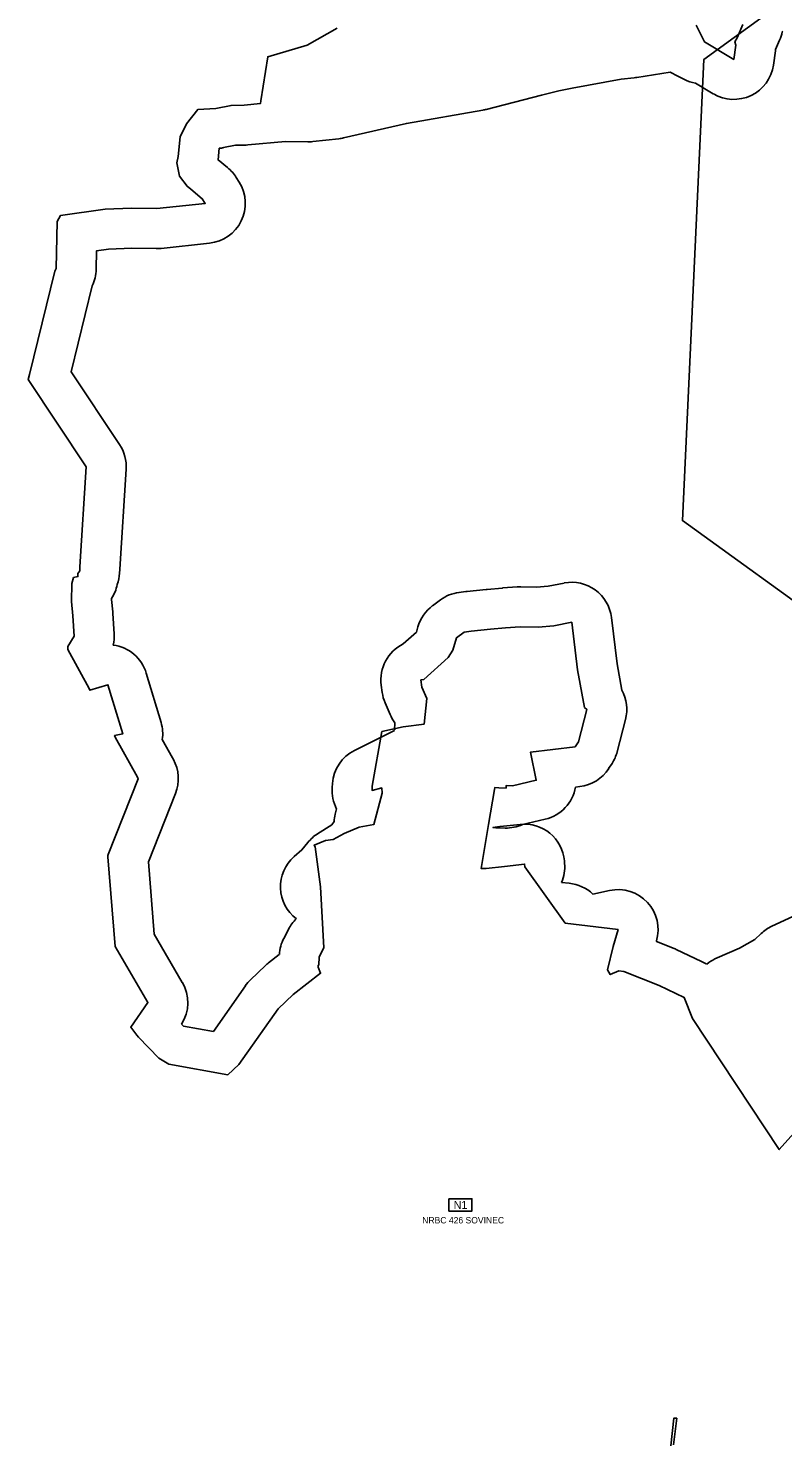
# Model space of a CAD drawing. Extents: x -547623 to -532764, y -1096714 to -1086523.
# Drawn here: x -545672 to -544729, y -1094393 to -1092629 of the extents above; entities that cross this region are included whole.
import ezdxf

# ---------------------------------------------------------------- set-up
doc = ezdxf.new("R2010")
doc.units = 0
for name, color, linetype in [('Vrstva 22', 7, 'Continuous'), ('Vrstva 23', 7, 'Continuous'), ('Vrstva 25', 7, 'Continuous'), ('Vrstva 27', 7, 'Continuous'), ('Vrstva 36', 7, 'Continuous')]:
    doc.layers.add(name, color=color, linetype=linetype)

msp = doc.modelspace()

# ---------------------------------------------------------------- linework, layer by layer
at = {"layer": 'Vrstva 22'}
msp.add_lwpolyline([(-544570.5, -1092481.5), (-544170.3, -1093428.5), (-544273.3, -1093653.1), (-544324, -1093623.3), (-544281.5, -1093528.2), (-544330.2, -1093474.1), (-544403.4, -1093457), (-544439.5, -1093470.8), (-544456.8, -1093510.2), (-544479, -1093516.1), (-544854.9, -1093244.4), (-544828, -1092667.9), (-544697.7, -1092572.9), (-544693.4, -1092540.6), (-544716.6, -1092493.7), (-544691.5, -1092459.6), (-544570.5, -1092481.5)], dxfattribs=at)
at = {"layer": 'Vrstva 23'}
for p, q in [((-544738.3, -1092655.5), (-544733.3, -1092644)), ((-544730.1, -1092633.5), (-544729.4, -1092632.5)), ((-544741.1, -1092675.1), (-544738.5, -1092657)), ((-544838.5, -1092697.6), (-544816.2, -1092710.9)), ((-545316.7, -1092770.6), (-545284.1, -1092767)), ((-545408.7, -1092821.5), (-545412.4, -1092815.6)), ((-545506.5, -1092904.1), (-545445.9, -1092897.6)), ((-545558, -1093305.2), (-545550, -1093180.2)), ((-545558.3, -1093310.2), (-545558, -1093305.3)), ((-545125.5, -1093333), (-545134.1, -1093334.1)), ((-545100, -1093330.4), (-545124.1, -1093332.8)), ((-545080, -1093328.7), (-545099, -1093330.3)), ((-545061.2, -1093327.3), (-545079.4, -1093328.6)), ((-545157.3, -1093343.5), (-545167.1, -1093350.8)), ((-545565.1, -1093386), (-545566.6, -1093360.6)), ((-545506.5, -1093496.8), (-545524.9, -1093435.2)), ((-545231.3, -1093450.2), (-545230.1, -1093459.1)), ((-545226.5, -1093472.2), (-545220.2, -1093486.7)), ((-545214.5, -1093506.6), (-545264.8, -1093531.7)), ((-545214.4, -1093499.7), (-545214.5, -1093503.7)), ((-544936.4, -1093533.3), (-544925.9, -1093493)), ((-545492.1, -1093541.1), (-545504.9, -1093518)), ((-545491.1, -1093543), (-545492.1, -1093541.1)), ((-544947, -1093554.4), (-544942.8, -1093547.9)), ((-545292.3, -1093572.9), (-545292.6, -1093578.1)), ((-544988.4, -1093577.5), (-544982.9, -1093576.8)), ((-545287, -1093604.8), (-545288.7, -1093611.5)), ((-545085.3, -1093628.5), (-545076.5, -1093628.7)), ((-545057.7, -1093624.1), (-545082.8, -1093626.9)), ((-545054.8, -1093624.3), (-545026.2, -1093617.6)), ((-545002.1, -1093672.9), (-545002.3, -1093669.7)), ((-544996.5, -1093697.7), (-545006, -1093696.8)), ((-544945.9, -1093706.8), (-544966.6, -1093711.4)), ((-545347.3, -1093755.4), (-545353.2, -1093766.7)), ((-545358.7, -1093786.9), (-545372.1, -1093797.3)), ((-544831.1, -1093795.3), (-544862.5, -1093780.4)), ((-545375.9, -1093800.5), (-545394.6, -1093818.3))]:
    msp.add_line(p, q, dxfattribs=at)
for points in [[(-545100.2, -1092730.4), (-545030.9, -1092712.5), (-545009.3, -1092707.2), (-544992.5, -1092704), (-544931.3, -1092692.4), (-544915.2, -1092690.9)], [(-544911.8, -1092690.5), (-544870.2, -1092683.8), (-544860.4, -1092688.8)], [(-544860.4, -1092688.9), (-544855.4, -1092691.4), (-544852.3, -1092693)], [(-545278.3, -1092766), (-545199.9, -1092747.9), (-545104.1, -1092731.2)], [(-545423.3, -1092803.2), (-545435.3, -1092793.5), (-545433.8, -1092779)], [(-545428.4, -1092778.2), (-545413.5, -1092775.3), (-545401.9, -1092775.1)], [(-545398.2, -1092774.8), (-545350.8, -1092770.4), (-545322.9, -1092770.8)], [(-545587.6, -1092930.3), (-545587.1, -1092907.1), (-545572, -1092905), (-545542.9, -1092903.9), (-545512.7, -1092904.4)], [(-545558.3, -1093149.3), (-545618.7, -1093058.5), (-545592.4, -1092950.9)], [(-545002.5, -1093322.4), (-545022.8, -1093326.2), (-545037, -1093327.6), (-545056.6, -1093327.2)], [(-545566.8, -1093358.4), (-545568.4, -1093343.2), (-545568.4, -1093341.6)], [(-544930.5, -1093456.2), (-544936.5, -1093423.4), (-544943.6, -1093365.4)], [(-545185.4, -1093377.2), (-545187.3, -1093383.8), (-545203.8, -1093398.6)], [(-545479.9, -1093821.6), (-545515.1, -1093761.4), (-545522.2, -1093670.8), (-545488.4, -1093585.6)], [(-545290.2, -1093620.6), (-545293.2, -1093624.6), (-545310.8, -1093635.8)], [(-545082.9, -1093626.9), (-545091.6, -1093627.9), (-545091, -1093628)], [(-545322.9, -1093646.7), (-545330.5, -1093656.1), (-545340, -1093664.4)], [(-544704.7, -1093726.5), (-544717, -1093739.2), (-544743, -1093751.4)], [(-544865.1, -1093779.3), (-544887.4, -1093770.3), (-544887.2, -1093769.8)], [(-544756.3, -1093760.6), (-544764.1, -1093768.1), (-544783.3, -1093778.9), (-544811.5, -1093791)], [(-544821.7, -1093796.8), (-544824.5, -1093799)], [(-545401.1, -1093825.9), (-545441.1, -1093882.9), (-545478.5, -1093876.2), (-545480.8, -1093873.8)]]:
    msp.add_lwpolyline(points, dxfattribs=at)
for centre, start, end in [((-544779.2, -1092624.1), 336.494, 349.1271), ((-544788, -1092649.9), 351.7946, 353.5151), ((-544790.6, -1092667.9), 239.2389, 351.7946), ((-544919.8, -1092641.1), 275.2056, 279.1028), ((-544837.7, -1092644.3), 243.0155, 243.028), ((-544829.5, -1092648.5), 242.9247, 259.6614), ((-545112.6, -1092681.9), 279.8671, 284.4331), ((-545289.6, -1092717.3), 276.2148, 283.0392), ((-545438.1, -1092729.2), 274.8718, 281.2179), ((-545402.8, -1092725.1), 271.1408, 275.3264), ((-545322.2, -1092720.9), 269.1388, 276.2148), ((-545454.9, -1092842), 31.8565, 50.8882), ((-545451.2, -1092847.9), 276.1075, 31.8565), ((-545511.8, -1092854.4), 268.9847, 276.1075), ((-545637.6, -1092929.4), 334.5, 358.9069), ((-545599.9, -1093177), 356.3255, 33.6791), ((-545608.2, -1093307), 339.7155, 356.316), ((-545607.9, -1093302), 356.316, 356.3255), ((-545610.3, -1093314.4), 326.9849, 348.5168), ((-545118.9, -1093382.6), 95.8916, 97.4941), ((-545094.8, -1093380.1), 94.7636, 95.8916), ((-545075.9, -1093378.5), 94.099, 94.7636), ((-545057.6, -1093377.2), 88.8267, 94.099), ((-544993.2, -1093371.5), 7.0039, 100.6751), ((-545137.3, -1093390.9), 126.512, 164.0497), ((-545127.5, -1093383.7), 97.4941, 126.512), ((-545616.6, -1093363.6), 3.4206, 5.9663), ((-545615, -1093389), 347.4093, 3.4206), ((-545572.8, -1093449.5), 16.6318, 82.4869), ((-545181.7, -1093443.5), 116.1197, 187.662), ((-544974.3, -1093480.4), 345.4375, 28.9048), ((-545180.5, -1093452.4), 187.662, 203.3321), ((-545174.3, -1093466.9), 203.3321, 216.9676), ((-545554.4, -1093511.1), 352.0228, 16.6318), ((-545164.5, -1093504.9), 178.5498, 181.8409), ((-545164.4, -1093501), 175.3978, 178.5498), ((-545535.9, -1093565.2), 28.8461, 28.9276), ((-545534.9, -1093567.1), 338.331, 28.8461), ((-545242.4, -1093576.4), 116.5735, 175.9858), ((-544984.8, -1093520.8), 327.0763, 345.4375), ((-544988.9, -1093527.2), 276.9131, 327.0763), ((-545242.8, -1093581.6), 175.9858, 207.7449), ((-545037.6, -1093568.9), 283.2155, 350.1418), ((-545240.4, -1093624.1), 165.3672, 175.9708), ((-545084.1, -1093578.5), 262.0716, 268.5695), ((-545077.2, -1093676.6), 96.3502, 96.4504), ((-545075.2, -1093578.7), 268.5695, 294.1821), ((-545052.2, -1093673.8), 4.7931, 96.3502), ((-545283.9, -1093678), 122.5187, 141.3025), ((-545307.3, -1093702.2), 130.9043, 233.0071), ((-545051.9, -1093677.1), 336.7432, 4.7931), ((-545001.2, -1093747.5), 46.2482, 84.5691), ((-544935.2, -1093755.6), 343.5003, 102.3722), ((-545302.9, -1093778.3), 133.6234, 152.6901), ((-544721.7, -1093796.6), 115.2407, 133.9137), ((-545308.7, -1093789.6), 152.6901, 176.8401), ((-544883.8, -1093825.6), 64.7136, 68.0222), ((-544791.9, -1093837), 113.1828, 126.5915), ((-545341.5, -1093836.8), 127.8058, 133.4586), ((-544852.5, -1093840.5), 56.0571, 64.7136), ((-545523, -1093846.9), 327.4678, 30.3468), ((-545360.2, -1093854.6), 133.4586, 145.003)]:
    msp.add_arc(centre, 50, start, end, dxfattribs=at)
at = {"layer": 'Vrstva 25'}
for points in [[(-544837.6, -1092625), (-544827.3, -1092646.1), (-544790.6, -1092667.9), (-544788, -1092649.9), (-544789.4, -1092646), (-544786.5, -1092640.9), (-544779.2, -1092624.1)], [(-544685.6, -1093976.9), (-544733.7, -1094030.6), (-544842.2, -1093866.8), (-544852.5, -1093840.5), (-544883.8, -1093825.6), (-544928, -1093807.8), (-544934.4, -1093807.3), (-544945, -1093811.9), (-544948.6, -1093806), (-544941.4, -1093776.7), (-544935.2, -1093755.6), (-545001.2, -1093747.5), (-545051.9, -1093677.1), (-545052.2, -1093673.8), (-545077.2, -1093676.6), (-545100.1, -1093679.2), (-545106.4, -1093679.1), (-545097.2, -1093624.2), (-545089.7, -1093580.7), (-545089.1, -1093577.8), (-545084.1, -1093578.5), (-545075.2, -1093578.7), (-545075.1, -1093575.4), (-545067, -1093575.8), (-545037.6, -1093568.9), (-545044.8, -1093534), (-544988.9, -1093527.2), (-544984.8, -1093520.8), (-544974.3, -1093480.4), (-544977.3, -1093477.9), (-544985.9, -1093431), (-544993.2, -1093371.5), (-545015.7, -1093375.8), (-545035.1, -1093377.7), (-545057.6, -1093377.2), (-545075.9, -1093378.5), (-545094.8, -1093380.1), (-545118.9, -1093382.6), (-545127.5, -1093383.7), (-545137.3, -1093390.9), (-545141.7, -1093406.4), (-545147.8, -1093415.5), (-545178.1, -1093442.8), (-545181.7, -1093443.5), (-545180.5, -1093452.4), (-545174.3, -1093466.9), (-545177.8, -1093498.7), (-545203.9, -1093502.2), (-545230.5, -1093508.2), (-545242.4, -1093576.4), (-545242.8, -1093581.6), (-545230.7, -1093578.5), (-545230.2, -1093585.1), (-545240.4, -1093624.1), (-545258.7, -1093627.4), (-545277.8, -1093635.4), (-545291.5, -1093643.1), (-545300.9, -1093644.3), (-545315.3, -1093650.2), (-545313.8, -1093652.2), (-545307.3, -1093702.2), (-545302.9, -1093778.3), (-545308.7, -1093789.6), (-545309.2, -1093799.9), (-545310, -1093799.9), (-545310, -1093802.7), (-545307, -1093810.1), (-545341.5, -1093836.8), (-545360.2, -1093854.6), (-545409.1, -1093924.4), (-545423, -1093937), (-545496.6, -1093923.8), (-545509.3, -1093916.2), (-545534.7, -1093890.2), (-545536.7, -1093887.6), (-545544.4, -1093877.5), (-545523, -1093846.9), (-545564, -1093776.8), (-545572.9, -1093664.6), (-545573, -1093663.1), (-545572.5, -1093661.9), (-545534.9, -1093567.1), (-545535.9, -1093565.2), (-545563.7, -1093515), (-545564.6, -1093513.2), (-545554.4, -1093511.1), (-545572.8, -1093449.5), (-545595.4, -1093456.4), (-545596.5, -1093454.3), (-545623, -1093405.3), (-545622.8, -1093401.6), (-545615, -1093389), (-545616.6, -1093363.6), (-545618.5, -1093345.4), (-545618.1, -1093322.8), (-545615.9, -1093315.6), (-545610.3, -1093314.4), (-545610.7, -1093310.6), (-545608.2, -1093307), (-545607.9, -1093302), (-545599.9, -1093177), (-545672.5, -1093068), (-545670.9, -1093061.7), (-545639.4, -1092932.6), (-545637.6, -1092929.4), (-545636.4, -1092870.7), (-545632.1, -1092862.9), (-545576.4, -1092855.1), (-545543.4, -1092853.8), (-545511.8, -1092854.4), (-545451.2, -1092847.9), (-545454.9, -1092842), (-545469.3, -1092830.3), (-545474, -1092826.5), (-545483.6, -1092813.9), (-545486.9, -1092797.2), (-545485.1, -1092789.1), (-545482.7, -1092764.8), (-545474.5, -1092748.5), (-545460.6, -1092730.6), (-545438.1, -1092729.2), (-545418.9, -1092725.4), (-545402.8, -1092725.1), (-545382.3, -1092723.1), (-545381.8, -1092719.7), (-545373.1, -1092664.6), (-545323.7, -1092650), (-545286.5, -1092628.7)], [(-544869.2, -1094401.1), (-544865.7, -1094366.4), (-544862, -1094366.4), (-544866.1, -1094399.8)]]:
    msp.add_lwpolyline(points, dxfattribs=at)
at = {"layer": 'Vrstva 27'}
for points in [[(-544837.6, -1092625), (-544827.3, -1092646.1), (-544790.6, -1092667.9), (-544788, -1092649.9), (-544789.4, -1092646), (-544786.5, -1092640.9), (-544779.2, -1092624.1)], [(-544685.6, -1093976.9), (-544733.7, -1094030.6), (-544842.2, -1093866.8), (-544852.5, -1093840.5), (-544883.8, -1093825.6), (-544928, -1093807.8), (-544934.4, -1093807.3), (-544945, -1093811.9), (-544948.6, -1093806), (-544941.4, -1093776.7), (-544935.2, -1093755.6), (-545001.2, -1093747.5), (-545051.9, -1093677.1), (-545052.2, -1093673.8), (-545077.2, -1093676.6), (-545100.1, -1093679.2), (-545106.4, -1093679.1), (-545097.2, -1093624.2), (-545089.7, -1093580.7), (-545089.1, -1093577.8), (-545084.1, -1093578.5), (-545075.2, -1093578.7), (-545075.1, -1093575.4), (-545067, -1093575.8), (-545037.6, -1093568.9), (-545044.8, -1093534), (-544988.9, -1093527.2), (-544984.8, -1093520.8), (-544974.3, -1093480.4), (-544977.3, -1093477.9), (-544985.9, -1093431), (-544993.2, -1093371.5), (-545015.7, -1093375.8), (-545035.1, -1093377.7), (-545057.6, -1093377.2), (-545075.9, -1093378.5), (-545094.8, -1093380.1), (-545118.9, -1093382.6), (-545127.5, -1093383.7), (-545137.3, -1093390.9), (-545141.7, -1093406.4), (-545147.8, -1093415.5), (-545178.1, -1093442.8), (-545181.7, -1093443.5), (-545180.5, -1093452.4), (-545174.3, -1093466.9), (-545177.8, -1093498.7), (-545203.9, -1093502.2), (-545230.5, -1093508.2), (-545242.4, -1093576.4), (-545242.8, -1093581.6), (-545230.7, -1093578.5), (-545230.2, -1093585.1), (-545240.4, -1093624.1), (-545258.7, -1093627.4), (-545277.8, -1093635.4), (-545291.5, -1093643.1), (-545300.9, -1093644.3), (-545315.3, -1093650.2), (-545313.8, -1093652.2), (-545307.3, -1093702.2), (-545302.9, -1093778.3), (-545308.7, -1093789.6), (-545309.2, -1093799.9), (-545310, -1093799.9), (-545310, -1093802.7), (-545307, -1093810.1), (-545341.5, -1093836.8), (-545360.2, -1093854.6), (-545409.1, -1093924.4), (-545423, -1093937), (-545496.6, -1093923.8), (-545509.3, -1093916.2), (-545534.7, -1093890.2), (-545536.7, -1093887.6), (-545544.4, -1093877.5), (-545523, -1093846.9), (-545564, -1093776.8), (-545572.9, -1093664.6), (-545573, -1093663.1), (-545572.5, -1093661.9), (-545534.9, -1093567.1), (-545535.9, -1093565.2), (-545563.7, -1093515), (-545564.6, -1093513.2), (-545554.4, -1093511.1), (-545572.8, -1093449.5), (-545595.4, -1093456.4), (-545596.5, -1093454.3), (-545623, -1093405.3), (-545622.8, -1093401.6), (-545615, -1093389), (-545616.6, -1093363.6), (-545618.5, -1093345.4), (-545618.1, -1093322.8), (-545615.9, -1093315.6), (-545610.3, -1093314.4), (-545610.7, -1093310.6), (-545608.2, -1093307), (-545607.9, -1093302), (-545599.9, -1093177), (-545672.5, -1093068), (-545670.9, -1093061.7), (-545639.4, -1092932.6), (-545637.6, -1092929.4), (-545636.4, -1092870.7), (-545632.1, -1092862.9), (-545576.4, -1092855.1), (-545543.4, -1092853.8), (-545511.8, -1092854.4), (-545451.2, -1092847.9), (-545454.9, -1092842), (-545469.3, -1092830.3), (-545474, -1092826.5), (-545483.6, -1092813.9), (-545486.9, -1092797.2), (-545485.1, -1092789.1), (-545482.7, -1092764.8), (-545474.5, -1092748.5), (-545460.6, -1092730.6), (-545438.1, -1092729.2), (-545418.9, -1092725.4), (-545402.8, -1092725.1), (-545382.3, -1092723.1), (-545381.8, -1092719.7), (-545373.1, -1092664.6), (-545323.7, -1092650), (-545286.5, -1092628.7)], [(-544869.2, -1094401.1), (-544865.7, -1094366.4), (-544862, -1094366.4), (-544866.1, -1094399.8)]]:
    msp.add_lwpolyline(points, dxfattribs=at)
at = {"layer": 'Vrstva 36'}
msp.add_lwpolyline([(-545146.6, -1094092), (-545118, -1094092), (-545118, -1094107.5), (-545146.6, -1094107.5)], close=True, dxfattribs=at)

# ---------------------------------------------------------------- texts
for s, height, p in [('N1', 10, (-545140.7, -1094104.7)), ('NRBC 426 SOVINEC', 8, (-545180, -1094122.9))]:
    msp.add_text(s, height=height, dxfattribs=at).set_placement(p)

doc.saveas('drawing.dxf')
